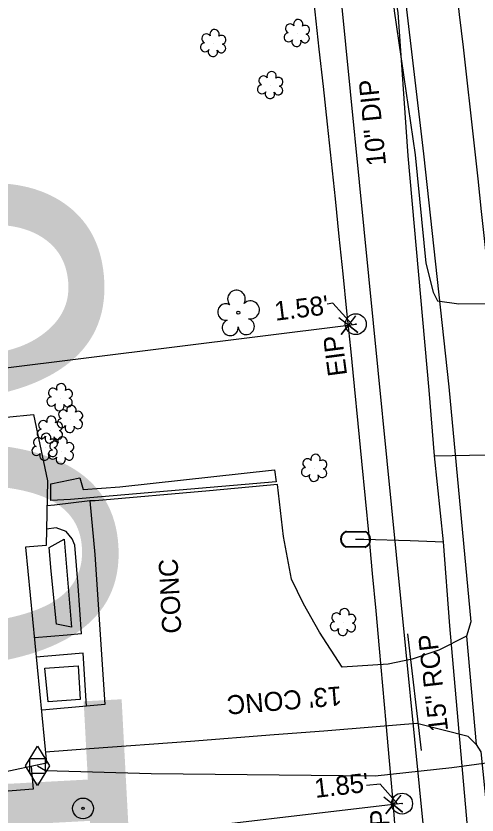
# Model space of a CAD drawing. Extents: x 2364404 to 2371833, y 798876 to 809754.
# Drawn here: x 2368671.1 to 2368767.9, y 804857.6 to 805025.4 of the extents above; entities that cross this region are included whole.
import ezdxf

# ---------------------------------------------------------------- set-up
doc = ezdxf.new("R2010")
doc.units = 0
for name, color, linetype in [('Exist Building', 7, 'Continuous'), ('Exist Horizontal Baseline Alignment Station Label', 7, 'Continuous'), ('Exist Other Culture Area Outline', 7, 'Continuous'), ('Exist Other Culture Fence Line', 7, 'Continuous'), ('Exist Other Culture Located Object CELL', 7, 'Continuous'), ('Exist Property Corner CELL', 7, 'Continuous'), ('Exist Property Iron Pin CELL', 7, 'Continuous'), ('Exist Property Iron Pin Text', 7, 'Continuous'), ('Exist Property Line', 7, 'Continuous'), ('Exist Property Line Leader', 7, 'Continuous'), ('Exist Property Line Text', 7, 'Continuous'), ('Exist Right of Way Line', 7, 'Continuous'), ('Exist Roads EOP', 7, 'Continuous'), ('Exist Roads EOP Other', 7, 'Continuous'), ('Exist Roads EOP Other Text', 7, 'Continuous'), ('Exist Structure Minor Pipes RCP 15 Inch', 7, 'Continuous'), ('Exist Structure Minor Pipes RCP 15 Inch Text', 7, 'Continuous'), ('Exist Utilities Gas Meter CELL', 7, 'Continuous'), ('Exist Utilities Gas UG Line SUE LOS B', 7, 'Continuous'), ('Exist Utilities Sanitary Sewer UG Line', 7, 'Continuous'), ('Exist Utilities Sanitary Sewer UG Line Text', 7, 'Continuous'), ('Exist Utilities TV UG Cable SUE LOS B', 7, 'Continuous'), ('Exist Utilities Water Meter CELL', 7, 'Continuous'), ('Exist Utilities Water UG Line SUE LOS B', 7, 'Continuous'), ('Exist Vegetation Hedge Row', 7, 'Continuous'), ('Exist Vegetation Shrub CELL', 7, 'Continuous'), ('Exist Vegetation Tree CELL', 7, 'Continuous'), ('Prop Horizontal Alignment', 7, 'Continuous')]:
    doc.layers.add(name, color=color, linetype=linetype)

msp = doc.modelspace()

# ---------------------------------------------------------------- linework, layer by layer
at = {"layer": 'Exist Building'}
msp.add_lwpolyline([(2368641.93, 804870.98), (2368635.86, 804935.29), (2368653.14, 804938.74), (2368663.57, 804938.83), (2368663.41, 804940.63), (2368674.81, 804941.69), (2368677.74, 804927.79), (2368677.42, 804914.18), (2368673.15, 804913.84), (2368677.51, 804868.46), (2368661, 804864.98), (2368644.68, 804865.07), (2368644.11, 804871.19)], close=True, dxfattribs=at)
at = {"layer": 'Exist Other Culture Area Outline'}
for points in [[(2368686.61, 804923.6), (2368679.18, 804922.69), (2368677.62, 804922.55)], [(2368684.88, 804895.68), (2368684.19, 804905.76), (2368683.45, 804914.25), (2368682.88, 804915.6), (2368681.63, 804917.15), (2368679.58, 804917.89), (2368677.5, 804917.61)], [(2368684.88, 804895.68), (2368681.83, 804895.4), (2368674.98, 804894.82)], [(2368685.95, 804880.49), (2368685.2, 804891.59), (2368681.1, 804891.25), (2368675.37, 804890.76)]]:
    msp.add_lwpolyline(points, dxfattribs=at)
at = {"layer": 'Exist Other Culture Fence Line'}
msp.add_lwpolyline([(2368674.34, 804867.8), (2368674.72, 804863.04), (2368666.77, 804862.38)], dxfattribs=at)
at = {"layer": 'Exist Other Culture Located Object CELL'}
for radius in [2.18, 0.24]:
    msp.add_circle((2368685.19, 804858.99), radius, dxfattribs=at)
at = {"layer": 'Exist Property Corner CELL'}
for p, q in [((2368740.89, 804960.5), (2368740.89, 804960.5)), ((2368750.32, 804859.79), (2368750.32, 804859.79))]:
    msp.add_line(p, q, dxfattribs=at)
for points in [[(2368742.42, 804962.48), (2368739.35, 804958.53), (2368740.89, 804960.5), (2368742.86, 804958.97), (2368738.91, 804962.04)], [(2368751.87, 804861.75), (2368748.77, 804857.82), (2368750.32, 804859.79), (2368752.28, 804858.23), (2368748.36, 804861.34)]]:
    msp.add_lwpolyline(points, dxfattribs=at)
at = {"layer": 'Exist Property Iron Pin CELL'}
for centre, radius in [((2368742.45, 804960.7), 2.2), ((2368742.45, 804960.7), 0.0707), ((2368752.16, 804860), 2.2), ((2368752.16, 804860), 0.0707)]:
    msp.add_circle(centre, radius, dxfattribs=at)
at = {"layer": 'Exist Property Line'}
for p, q in [((2368537.44, 804935.15), (2368740.89, 804960.5)), ((2368740.89, 804960.5), (2368742.45, 804960.7)), ((2368750.32, 804859.79), (2368546.95, 804836.06)), ((2368752.16, 804860), (2368750.32, 804859.79))]:
    msp.add_line(p, q, dxfattribs=at)
at = {"layer": 'Exist Property Line Leader'}
for points in [[(2368741.67, 804960.6), (2368737.61, 804965.08), (2368736.43, 804964.91)], [(2368751.24, 804859.89), (2368747.57, 804864.09), (2368744.72, 804863.83)]]:
    msp.add_lwpolyline(points, dxfattribs=at)
at = {"layer": 'Exist Right of Way Line'}
msp.add_arc((2362003.23, 804278.6), 6772.08, 3.19565, 7.475854, dxfattribs=at)
at = {"layer": 'Exist Roads EOP'}
msp.add_lwpolyline([(2368735.38, 805160.77), (2368738.1, 805145.25), (2368744.78, 805095.56), (2368750.88, 805045.92), (2368756.64, 804996.46), (2368762, 804947.56), (2368766.63, 804898.17), (2368765.7, 804895.17), (2368767.73, 804872.42), (2368768.67, 804870.88), (2368770.89, 804849.51), (2368774.62, 804798.63)], dxfattribs=at)
at = {"layer": 'Exist Roads EOP Other'}
for points in [[(2368765.7, 804895.17), (2368759.86, 804892.21), (2368754.31, 804890.35), (2368749.24, 804889.27), (2368739.61, 804888.65), (2368734.86, 804896.01), (2368731.48, 804901.93), (2368728.98, 804907.13), (2368727.25, 804916.12), (2368726, 804927.03), (2368711.74, 804925.71), (2368687.71, 804923.59), (2368686.61, 804923.6), (2368687.64, 804912.3), (2368689.8, 804880.8), (2368685.95, 804880.49), (2368677.38, 804879.71), (2368676.44, 804879.64)], [(2368767.73, 804872.42), (2368766.06, 804874.07), (2368755.25, 804876.82), (2368746.73, 804876.11), (2368735.73, 804875.2), (2368725.3, 804874.47), (2368707.72, 804873.02), (2368686.52, 804871.51), (2368677.28, 804870.81)]]:
    msp.add_lwpolyline(points, dxfattribs=at)
at = {"layer": 'Exist Structure Minor Pipes RCP 15 Inch'}
msp.add_line((2368756.26, 804871.13), (2368753.4, 804895.64), dxfattribs=at)
at = {"layer": 'Exist Utilities Gas Meter CELL'}
msp.add_line((2368675.63, 804867.92), (2368675.63, 804867.92), dxfattribs=at)
for points in [[(2368673.1, 804867.92), (2368675.63, 804872.03), (2368678.17, 804867.92), (2368675.63, 804863.81), (2368673.1, 804867.92)], [(2368674.06, 804869.46), (2368677.21, 804869.46), (2368677.21, 804866.34), (2368674.06, 804866.34), (2368674.06, 804869.46)]]:
    msp.add_lwpolyline(points, dxfattribs=at)
at = {"layer": 'Exist Utilities Gas UG Line SUE LOS B'}
msp.add_lwpolyline([(2368675.63, 804867.92), (2368677.29, 804866.93), (2368699.52, 804866.3), (2368746.49, 804865.81), (2368762.62, 804867.57), (2368789.01, 804871.12), (2368791.5, 804871.49)], dxfattribs=at)
at = {"layer": 'Exist Utilities Sanitary Sewer UG Line'}
msp.add_line((2368723.31, 805190.69), (2368757.51, 804845.61), dxfattribs=at)
at = {"layer": 'Exist Utilities TV UG Cable SUE LOS B'}
msp.add_lwpolyline([(2368726.52, 805059.99), (2368728.83, 805060.26), (2368731.14, 805060.23), (2368744.59, 805060.65), (2368746.16, 805060.05), (2368748.65, 805045.71), (2368750.5, 805026.48), (2368754.91, 804996.29), (2368757.16, 804973.51), (2368758.66, 804967.44), (2368759.59, 804965.58), (2368764.11, 804964.94), (2368781.44, 804965.05), (2368798.59, 804964.15), (2368826.29, 804964.48), (2368874.02, 804962.77)], dxfattribs=at)
at = {"layer": 'Exist Utilities Water Meter CELL'}
msp.add_line((2368742.42, 804915.51), (2368742.42, 804915.51), dxfattribs=at)
for points in [[(2368740.4, 804917.24), (2368744.48, 804917.18)], [(2368740.4, 804917.1), (2368744.47, 804917.05)], [(2368744.43, 804913.92), (2368740.33, 804913.98)], [(2368744.43, 804913.78), (2368740.33, 804913.84)]]:
    msp.add_lwpolyline(points, dxfattribs=at)
for centre, radius, start, end in [((2368741.11, 804915.52), 1.86, 112.4242, 245.2256), ((2368741.12, 804915.52), 1.73, 114.5471, 243.0285), ((2368743.71, 804915.49), 1.86, 292.8945, 65.5546), ((2368743.72, 804915.49), 1.73, 294.3734, 64.119)]:
    msp.add_arc(centre, radius, start, end, dxfattribs=at)
at = {"layer": 'Exist Utilities Water UG Line SUE LOS B'}
for points in [[(2368766.48, 804848.84), (2368762.16, 804897.33), (2368760.87, 804914.96), (2368758.99, 804933.04), (2368757.83, 804946.83), (2368753.42, 804996.06), (2368751.33, 805026.16), (2368748.05, 805045.41), (2368741.67, 805094.72), (2368740.94, 805101.54), (2368734.11, 805144.64), (2368728.26, 805184.75), (2368726.53, 805193.75), (2368721.63, 805243.92), (2368715.69, 805292.83)], [(2368758.99, 804933.04), (2368788.41, 804933.57), (2368802.46, 804935.11), (2368803.99, 804935.39), (2368803.99, 804935.39)], [(2368742.42, 804915.51), (2368744.14, 804915.55), (2368753.88, 804915.27), (2368760.87, 804914.96)]]:
    msp.add_lwpolyline(points, dxfattribs=at)
at = {"layer": 'Exist Vegetation Hedge Row'}
for points in [[(2368725.7, 804927.57), (2368682.53, 804923.86), (2368678.4, 804923.65), (2368678.42, 804927.19), (2368684.5, 804928.4), (2368685.23, 804925.97), (2368692.95, 804926.52), (2368725.38, 804930.08), (2368725.7, 804927.57)], [(2368681.26, 804915.52), (2368682.79, 804897.03), (2368679.63, 804897.72), (2368678.49, 804908.85), (2368678.08, 804913.8), (2368681.26, 804915.52)], [(2368684.14, 804888.95), (2368684.61, 804881.86), (2368677.85, 804881.38), (2368677.18, 804888.43), (2368684.14, 804888.95)]]:
    msp.add_lwpolyline(points, dxfattribs=at)
at = {"layer": 'Exist Vegetation Shrub CELL'}
for p, q in [((2368730.13, 805021.66), (2368730.13, 805021.66)), ((2368712.58, 805019.56), (2368712.58, 805019.56)), ((2368724.55, 805010.72), (2368724.55, 805010.72)), ((2368680.37, 804945.17), (2368680.37, 804945.17)), ((2368682.52, 804940.6), (2368682.52, 804940.6)), ((2368678.32, 804938.36), (2368678.32, 804938.36)), ((2368677.22, 804934.77), (2368677.22, 804934.77)), ((2368680.65, 804934.01), (2368680.65, 804934.01)), ((2368733.78, 804930.34), (2368733.78, 804930.34)), ((2368739.84, 804897.95), (2368739.84, 804897.95))]:
    msp.add_line(p, q, dxfattribs=at)
for centre, radius, start, end in [((2368728.65, 805022.78), 0.968, 35.8908, 245.4216), ((2368730.36, 805023.7), 0.99, 334.8391, 200.4717), ((2368712.8, 805021.6), 0.99, 334.8391, 200.4717), ((2368731.8, 805022.53), 0.929, 284.4567, 126.0861), ((2368711.09, 805020.69), 0.968, 35.8908, 245.4216), ((2368714.25, 805020.43), 0.929, 284.4567, 126.0861), ((2368728.33, 805020.95), 0.955, 95.1099, 327.9534), ((2368730, 805019.97), 0.984, 151.2797, 21.387), ((2368731.77, 805020.73), 0.937, 204.9913, 73.4601), ((2368710.78, 805018.85), 0.955, 95.1099, 327.9534), ((2368714.21, 805018.63), 0.937, 204.9913, 73.4601), ((2368712.45, 805017.88), 0.984, 151.2797, 21.387), ((2368724.78, 805012.76), 0.99, 334.8391, 200.4717), ((2368723.07, 805011.85), 0.968, 35.8908, 245.4216), ((2368726.22, 805011.59), 0.929, 284.4567, 126.0861), ((2368722.75, 805010.01), 0.955, 95.1099, 327.9534), ((2368726.19, 805009.79), 0.937, 204.9913, 73.4601), ((2368724.42, 805009.04), 0.984, 151.2797, 21.387), ((2368680.6, 804947.21), 0.99, 334.8391, 200.4717), ((2368678.89, 804946.29), 0.968, 35.8908, 245.4216), ((2368682.04, 804946.04), 0.929, 284.4567, 126.0861), ((2368678.57, 804944.46), 0.955, 95.1099, 327.9534), ((2368682.01, 804944.24), 0.937, 204.9913, 73.4601), ((2368680.24, 804943.48), 0.984, 151.2797, 21.387), ((2368682.75, 804942.64), 0.99, 334.8391, 200.4717), ((2368681.04, 804941.73), 0.968, 35.8908, 245.4216), ((2368684.2, 804941.47), 0.929, 284.4567, 126.0861), ((2368676.84, 804939.49), 0.968, 35.8908, 245.4216), ((2368678.55, 804940.4), 0.99, 334.8391, 200.4717), ((2368679.99, 804939.23), 0.929, 284.4567, 126.0861), ((2368680.72, 804939.9), 0.955, 95.1099, 327.9534), ((2368684.16, 804939.67), 0.937, 204.9913, 73.4601), ((2368676.52, 804937.66), 0.955, 95.1099, 327.9534), ((2368679.96, 804937.43), 0.937, 204.9913, 73.4601), ((2368682.4, 804938.92), 0.984, 151.2797, 21.387), ((2368675.74, 804935.89), 0.968, 35.8908, 245.4216), ((2368677.45, 804936.81), 0.99, 334.8391, 200.4717), ((2368678.19, 804936.68), 0.984, 151.2797, 21.387), ((2368678.89, 804935.64), 0.929, 284.4567, 126.0861), ((2368680.87, 804936.05), 0.99, 334.8391, 200.4717), ((2368675.42, 804934.06), 0.955, 95.1099, 327.9534), ((2368678.85, 804933.84), 0.937, 204.9913, 73.4601), ((2368679.16, 804935.13), 0.968, 35.8908, 245.4216), ((2368682.32, 804934.88), 0.929, 284.4567, 126.0861), ((2368677.09, 804933.08), 0.984, 151.2797, 21.387), ((2368678.85, 804933.3), 0.955, 95.1099, 327.9534), ((2368682.28, 804933.08), 0.937, 204.9913, 73.4601), ((2368734.01, 804932.38), 0.99, 334.8391, 200.4717), ((2368680.52, 804932.32), 0.984, 151.2797, 21.387), ((2368732.3, 804931.47), 0.968, 35.8908, 245.4216), ((2368735.45, 804931.21), 0.929, 284.4567, 126.0861), ((2368731.98, 804929.64), 0.955, 95.1099, 327.9534), ((2368735.42, 804929.41), 0.937, 204.9913, 73.4601), ((2368733.65, 804928.66), 0.984, 151.2797, 21.387), ((2368738.36, 804899.08), 0.968, 35.8908, 245.4216), ((2368740.07, 804899.99), 0.99, 334.8391, 200.4717), ((2368741.51, 804898.82), 0.929, 284.4567, 126.0861), ((2368738.04, 804897.25), 0.955, 95.1099, 327.9534), ((2368741.48, 804897.02), 0.937, 204.9913, 73.4601), ((2368739.71, 804896.27), 0.984, 151.2797, 21.387)]:
    msp.add_arc(centre, radius, start, end, dxfattribs=at)
at = {"layer": 'Exist Vegetation Tree CELL'}
msp.add_line((2368717.79, 804963.1), (2368717.79, 804963.1), dxfattribs=at)
msp.add_circle((2368717.79, 804963.1), 0.326, dxfattribs=at)
for centre, radius, start, end in [((2368717.4, 804965.97), 1.86, 330.1651, 219.7134), ((2368715.18, 804963.25), 1.73, 62.6636, 279.3457), ((2368720.34, 804963.69), 1.9, 257.1011, 134.1999), ((2368719.46, 804960.2), 1.7, 181.2822, 74.56), ((2368716.08, 804959.98), 1.69, 111.5671, 6.231)]:
    msp.add_arc(centre, radius, start, end, dxfattribs=at)
at = {"layer": 'Prop Horizontal Alignment'}
msp.add_arc((2363433, 804410.95), 5366.57, 2.79654, 7.54241, dxfattribs=at)

# ---------------------------------------------------------------- texts
at = {"layer": 'Exist Horizontal Baseline Alignment Station Label'}
msp.add_text('BL-106', height=73.5, rotation=93.0566, dxfattribs=at).set_placement((2368704.11, 804679.39))
at = {"layer": 'Exist Property Iron Pin Text'}
for rotation, p in [(97.4798, (2368740.64, 804950.02)), (93.0566, (2368749.83, 804850.26))]:
    msp.add_text('EIP', height=4, rotation=rotation, dxfattribs=at).set_placement(p)
at = {"layer": 'Exist Property Line Text'}
for s, rotation, p in [("1.58'", 7.1036, (2368725.61, 804961.4)), ("1.85'", 6.6536, (2368733.99, 804861.19))]:
    msp.add_text(s, height=4, rotation=rotation, dxfattribs=at).set_placement(p)
at = {"layer": 'Exist Roads EOP Other Text'}
for s, rotation, p in [(' CONC', 93.0566, (2368705.94, 804894.33)), ("13' CONC", 184.7219, (2368739.35, 804884.65))]:
    msp.add_text(s, height=4, rotation=rotation, dxfattribs=at).set_placement(p)
at = {"layer": 'Exist Structure Minor Pipes RCP 15 Inch Text'}
msp.add_text('15" RCP', height=4, rotation=96.646, dxfattribs=at).set_placement((2368761.85, 804875.33))
at = {"layer": 'Exist Utilities Sanitary Sewer UG Line Text'}
msp.add_text('10" DIP', height=4, rotation=95.6594, dxfattribs=at).set_placement((2368748.82, 804994.13))

doc.saveas('drawing.dxf')
